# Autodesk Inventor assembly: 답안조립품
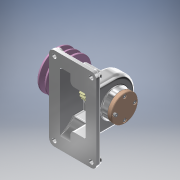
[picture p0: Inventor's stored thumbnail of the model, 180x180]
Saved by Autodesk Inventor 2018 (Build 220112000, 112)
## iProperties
Created: 2024-01
Part Number: 답안조립품
Material: 일반
Document SubType Name: Assembly
Designer: na
Author: na
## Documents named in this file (16)
- C:\Users\na\Desktop\740104V1005\답안조립품.iam
- C:\Users\na\Desktop\740104V1005\본체.ipt
- C:\Users\na\Desktop\740104V1005\깊은 홈 볼 베어링 6202.ipt
- C:\Users\na\Desktop\740104V1005\축.ipt
- C:\Users\na\Desktop\740104V1005\평행 키 5x5x32.ipt
- C:\Users\na\Desktop\740104V1005\평행 키 3x3x12.ipt
- C:\Users\na\Desktop\740104V1005\칼라.ipt
- C:\Users\na\Desktop\740104V1005\스퍼 기어.ipt
- C:\Users\na\Desktop\740104V1005\뒷커버.ipt
- C:\Users\na\Desktop\740104V1005\앞커버.ipt
- C:\Users\na\Desktop\740104V1005\오일 실 15 25 7.ipt
- C:\Users\na\Desktop\740104V1005\육각 소켓 머리 볼트 M4 x 12.ipt
- C:\Users\na\Desktop\740104V1005\V-벨트 풀리.ipt
- C:\Users\na\Desktop\740104V1005\엔드 캡.ipt
- C:\Users\na\Desktop\740104V1005\평와셔 M4.ipt
- C:\Users\na\Desktop\740104V1005\육각 머리 볼트 M4 x 12.ipt
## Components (1 placed, 1 different names)
1. V-벨트 풀리:1
